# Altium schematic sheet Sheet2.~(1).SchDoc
size A4
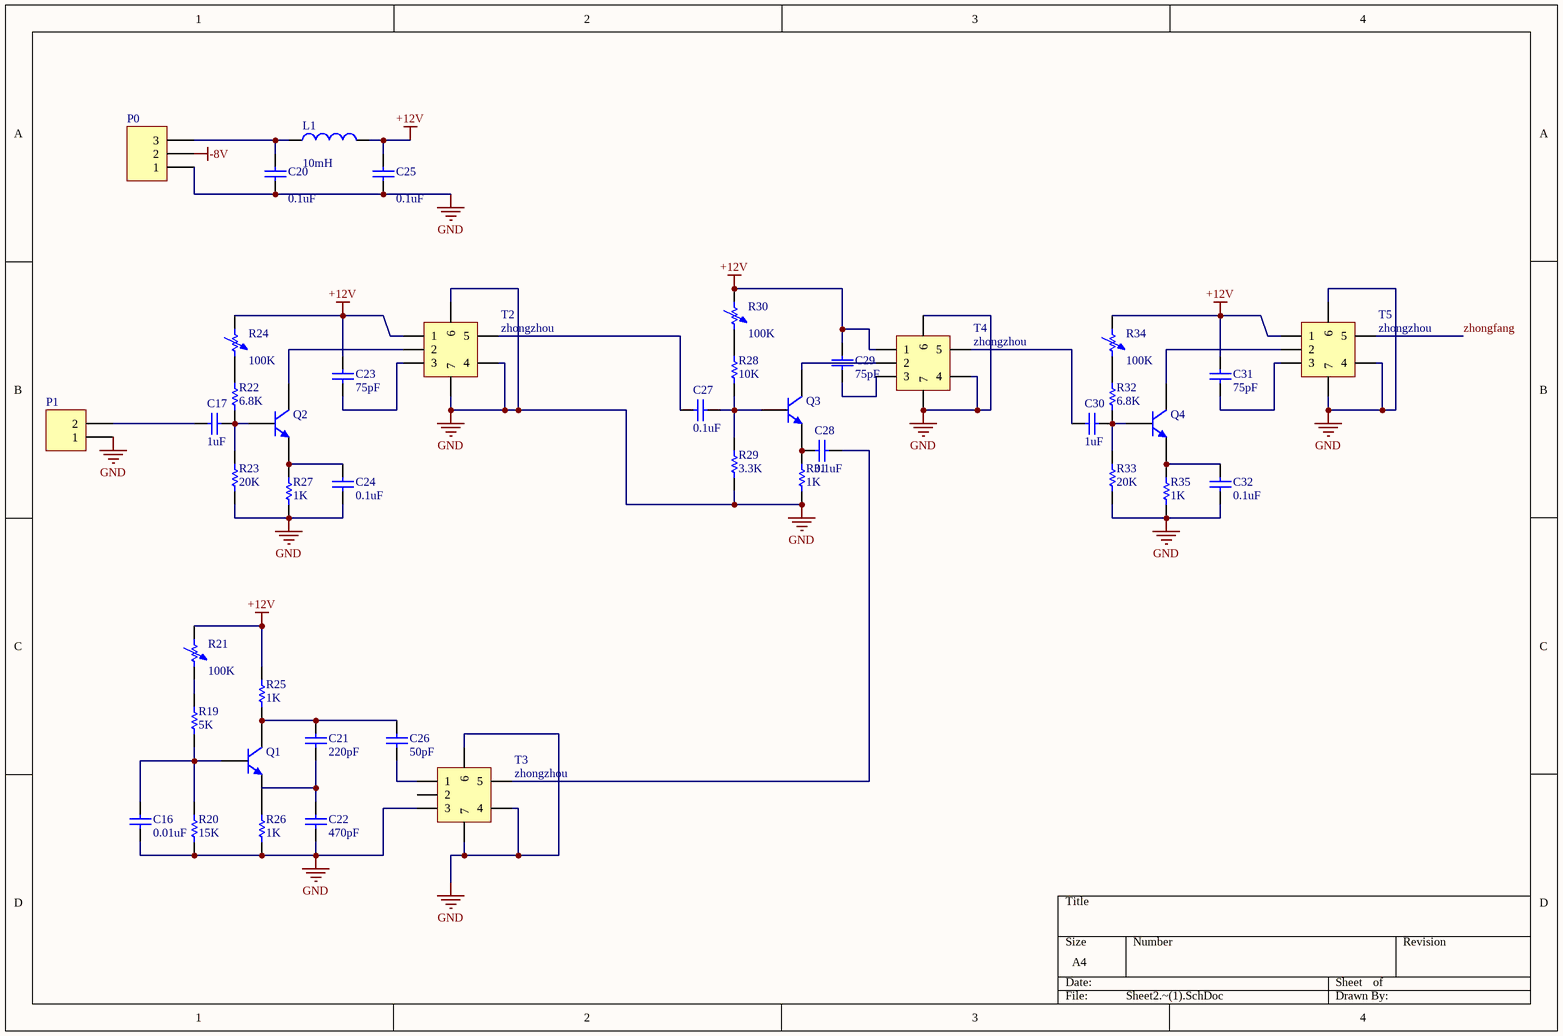
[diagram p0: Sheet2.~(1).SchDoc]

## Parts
C16  value 0.01uF  [2012[0805]]  (hidden comment: Cap)
C17  value 1uF  [2012[0805]]  (hidden comment: Cap)
C20  value 0.1uF  [RAD-0.3]  (hidden comment: Cap)
C21  value 220pF  [2012[0805]]  (hidden comment: Cap)
C22  value 470pF  [2012[0805]]  (hidden comment: Cap)
C23  value 75pF  [2012[0805]]  (hidden comment: Cap)
C24  value 0.1uF  [2012[0805]]  (hidden comment: Cap)
C25  value 0.1uF  [RAD-0.3]  (hidden comment: Cap)
C26  value 50pF  [2012[0805]]  (hidden comment: Cap)
C27  value 0.1uF  [2012[0805]]  (hidden comment: Cap)
C28  value 0.1uF  [2012[0805]]  (hidden comment: Cap)
C29  value 75pF  [2012[0805]]  (hidden comment: Cap)
C30  value 1uF  [2012[0805]]  (hidden comment: Cap)
C31  value 75pF  [2012[0805]]  (hidden comment: Cap)
C32  value 0.1uF  [2012[0805]]  (hidden comment: Cap)
L1  value 10mH  [0402-A]  (hidden comment: Inductor)
P0  Header 3  [HDR1X3]  (value not drawn)
P1  Header 2  [HDR1X2]  (value not drawn)
Q1  NPN  [TO-226]  (value not drawn)
Q2  NPN  [TO-226]  (value not drawn)
Q3  NPN  [TO-226]  (value not drawn)
Q4  NPN  [TO-226]  (value not drawn)
R19  value 5K  [2012[0805]]  (hidden comment: Res1)
R20  value 15K  [2012[0805]]  (hidden comment: Res1)
R21  value 100K  [AXIAL-0.7]  (hidden comment: Res Adj1)
R22  value 6.8K  [2012[0805]]  (hidden comment: Res1)
R23  value 20K  [2012[0805]]  (hidden comment: Res1)
R24  value 100K  [AXIAL-0.7]  (hidden comment: Res Adj1)
R25  value 1K  [2012[0805]]  (hidden comment: Res1)
R26  value 1K  [2012[0805]]  (hidden comment: Res1)
R27  value 1K  [2012[0805]]  (hidden comment: Res1)
R28  value 10K  [2012[0805]]  (hidden comment: Res1)
R29  value 3.3K  [2012[0805]]  (hidden comment: Res1)
R30  value 100K  [AXIAL-0.7]  (hidden comment: Res Adj1)
R31  value 1K  [2012[0805]]  (hidden comment: Res1)
R32  value 6.8K  [2012[0805]]  (hidden comment: Res1)
R33  value 20K  [2012[0805]]  (hidden comment: Res1)
R34  value 100K  [AXIAL-0.7]  (hidden comment: Res Adj1)
R35  value 1K  [2012[0805]]  (hidden comment: Res1)
T2  zhongzhou
T3  zhongzhou
T4  zhongzhou
T5  zhongzhou

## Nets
+12V: C23.1 C25.2 C29.1 C31.1 L1.2 R21.1 R24.1 R25.2 R30.1 R34.1 T2.1 T4.1 T5.1
-8V: P0.2
GND: C16.2 C20.1 C22.2 C24.1 C25.1 C32.1 P0.1 P1.1 R20.1 R23.1 R26.1 R27.1 R29.1 R31.1 R33.1 R35.1 T2.4 T2.6 T2.7 T3.3 T3.4 T3.6 T3.7 T4.4 T4.6 T4.7 T5.4 T5.6 T5.7
zhongfang: T5.5
NetC16_1: C16.1 Q1.2(B) R19.1 R20.2
NetC17_1: C17.1 P1.2
NetC17_2: C17.2 Q2.2(B) R22.1 R23.2
NetC20_2: C20.2 L1.1 P0.3
NetC21_1: C21.1 C26.2 Q1.1(C) R25.1
NetC21_2: C21.2 C22.1
NetC23_2: C23.2 T2.3
NetC24_2: C24.2 Q2.3(E) R27.2
NetC26_1: C26.1 T3.1
NetC27_1: C27.1 T2.5
NetC27_2: C27.2 Q3.2(B) R28.1 R29.2
NetC28_1: C28.1 Q3.3(E) R31.2
NetC28_2: C28.2 T3.5
NetC29_2: C29.2 T4.3
NetC30_1: C30.1 T4.5
NetC30_2: C30.2 Q4.2(B) R32.1 R33.2
NetC31_2: C31.2 T5.3
NetC32_2: C32.2 Q4.3(E) R35.2
NetQ1_3: Q1.3(E) R26.2
NetQ2_1: Q2.1(C) T2.2
NetQ3_1: Q3.1(C) T4.2
NetQ4_1: Q4.1(C) T5.2
NetR19_2: R19.2 R21.2
NetR22_2: R22.2 R24.2
NetR28_2: R28.2 R30.2
NetR32_2: R32.2 R34.2

Not connected (* = marked no-connect by the designer): T3 2

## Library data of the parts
C16 C17 C20-C32 = Cap: Capacitor
L1 = Inductor: Code_IEC: 1005
P0 = Header 3: Header, 3-Pin
P1 = Header 2: Header, 2-Pin
Q1-Q4 = NPN: NPN Bipolar Transistor
R19 R20 R22 R23 R25-R29 R31-R33 R35 = Res1: Resistor
R21 R24 R30 R34 = Res Adj1: Variable Resistor; Set Position: 0.5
